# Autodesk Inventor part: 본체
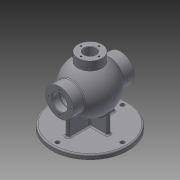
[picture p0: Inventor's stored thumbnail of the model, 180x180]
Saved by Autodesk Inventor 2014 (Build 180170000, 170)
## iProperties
Created: 2020-08
Part Number: 본체
Material: Generic
Document SubType Name: Modeling
Designer: kh
Density: 1 g/cm^3
Appearance: Default
Author: kh
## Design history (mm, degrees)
sketch "Sketch1"
  geometry: C1 r 85 at (0, 0); 1 further point
  constraints: 1 centre point, 1 coincident
  dimensions: "d0" = 170 diameter of C1
extrude "Extrusion1" new body sketch "Sketch1" distance "d1" = 10; taper "d2" = 0 deg
sketch "Sketch2"
  geometry: L1 (-68, 85)-(68, 85); A1 r 53 centre (0, 85) between (53, 85) and (-53, 85); 2 further points
  constraints: 2 end point, 2 point on circle, 2 point on line, 1 centre point, 1 coincident, 1 horizontal, 1 midpoint, 1 vertical alignment
  dimensions: "d3" = 136 distance of L1.start L1.end; "d4" = 85 distance from line of point (0, 0) L1; "d5" = 106 diameter of A1
revolve "Revolution1" sketch "Sketch2" stored, may be unused: angle "d6" = 90 deg
sketch "Sketch4"
  geometry: L1 (-68, 85)-(68, 85); L2 (-68, 102.5)-(-68, 116); L3 (-68, 116)-(-42.988, 116); L4 (-68, 102.5)-(-50.027, 102.5); L5 (-50.027, 102.5)-(-42.988, 102.5); L6 (-42.988, 116)-(-42.988, 102.5); A1 r 53 centre (0, 85) between (-42.988, 116) and (-50.027, 102.5) reference; 2 further points
  constraints: 12 end point, 3 perpendicular, 2 point on circle, 1 coincident, 1 collinear, 1 horizontal, 1 midpoint, 1 parallel, 1 vertical alignment
  dimensions: "d7" = 85 distance from line of point (0, 0) L1; "d8" = 136 distance of L1.start L1.end; "d9" = 35 diameter of L2.start L1; "d10" = 62 diameter of L2.end L1
revolve "Revolution2" sketch "Sketch4" stored, may be unused: angle "d11" = 90 deg
mirror "Mirror1"
sketch "Sketch5"
  geometry: L1 (43, 85)-(-43, 85); A1 r 53 centre (0, 85) between (42.988, 116) and (42.988, 54) reference; A2 r 53 centre (0, 85) between (50.027, 67.5) and (50.027, 102.5) reference; A3 r 53 centre (0, 85) between (50.027, 102.5) and (42.988, 116); A4 r 53 centre (0, 85) between (42.988, 54) and (50.027, 67.5); A5 r 43 centre (0, 85) between (-43, 85) and (43, 85); 1 further point
  constraints: 6 point on circle, 3 centre point, 3 coincident, 2 end point, 1 horizontal, 1 midpoint
  dimensions: "d12" = 86 diameter of A5
revolve "Revolution3" sketch "Sketch5" stored, may be unused: angle "d13" = 90 deg
workplane "Work Plane1"
sketch "Sketch7"
  geometry: C1 r 17.5 at (0, 0) reference; C2 r 17.5 at (0, 0); 1 further point
  constraints: 1 centre point, 1 coincident, 1 concentric
extrude "Extrusion2" cut sketch "Sketch7" stored distance "d15" = 10; taper "d16" = 0 deg
workplane "Work Plane2"
sketch "Sketch8"
  geometry: C1 r 27 at (0, 0); 1 further point
  constraints: 1 centre point, 1 coincident
  dimensions: "d18" = 54 diameter of C1
extrude "Extrusion3" join sketch "Sketch8" stored distance "d19" = 10; taper "d20" = 0 deg
sketch "Sketch9"
  geometry: C1 r 13 at (0, 0); 1 further point
  constraints: 1 centre point, 1 coincident
  dimensions: "d21" = 26 diameter of C1
extrude "Extrusion4" cut sketch "Sketch9" stored distance "d22" = 10; taper "d23" = 0 deg
sketch "Sketch10"
  geometry: 2 further points
  constraints: 1 vertical alignment
  dimensions: "d24" = 20 distance of point (0, 0) point (0, 20)
hole "Hole1" sketch "Sketch10" at (0, 20) diameter "d25" = 3.459; stored, may be unused: countersink angle "d29" = 90 deg, drill point angle "d31" = 118 deg; dims "d26" = 12, "d27" = 4, "d28" = 2, "d30" = 15
pattern_circular "Circular Pattern1" dims angle "d33" = 360 deg
sketch "Sketch11" dims "d35" = 48
  geometry: C1 r 31 at (0, 0) reference; 3 further points
  constraints: 2 vertical alignment, 1 coincident, 2 other
hole "Hole2" sketch "Sketch11" at (0, 24) diameter "d36" = 3.459; stored, may be unused: countersink angle "d40" = 90 deg, drill point angle "d42" = 118 deg; dims "d37" = 12, "d38" = 4, "d39" = 2, "d41" = 15
pattern_circular "Circular Pattern2" dims angle "d44" = 360 deg
mirror "Mirror2"
sketch "Sketch12"
  geometry: L1 (-4, -52)-(4, -52); L2 (4, -52)-(4, 52); L3 (4, 52)-(-4, 52); L4 (-4, 52)-(-4, -52); L5 (-4, -52)-(4, 52); L6 (4, -52)-(-4, 52); L7 (-43, -4)-(43, -4); L8 (43, -4)-(43, 4); L9 (43, 4)-(-43, 4); L10 (-43, 4)-(-43, -4); L11 (-43, -4)-(43, 4); L12 (43, -4)-(-43, 4); 1 further point
  constraints: 24 end point, 4 midpoint, 4 parallel, 2 horizontal, 2 perpendicular
  dimensions: "d47" = 8 distance of L3.end L2.end; "d48" = 104 distance of L2.end L1.end; "d49" = 86 distance of L9.end L8.end; "d50" = 8 distance of L8.end L7.end
extrude "Extrusion5" join sketch "Sketch12" stored distance "d51" = 10; taper "d52" = 0 deg
chamfer "Chamfer1" distance "d53" = 1; stored, may be unused: second distance "d54" = 2, angle "d55" = 45 deg
chamfer "Chamfer2" distance "d56" = 1; stored, may be unused: second distance "d57" = 2, angle "d58" = 45 deg
chamfer "Chamfer3" distance "d59" = 1; stored, may be unused: second distance "d60" = 2, angle "d61" = 45 deg
sketch "Sketch13"
  geometry: L1 (0, 85)-(-80.895, 85); L2 (-52, 85)-(-52, 103.5); L3 (-52, 103.5)-(-50.25, 103.5); L4 (-50.25, 103.5)-(-50.25, 85); L5 (-68, 103.5)-(-68, 66.5) reference; A1 r 43 centre (0, 85) between (-39.278, 67.5) and (-39.278, 102.5) reference; 1 further point
  constraints: 8 end point, 2 perpendicular, 2 point on line, 1 horizontal, 1 parallel
  dimensions: "d62" = 1.75 distance of L2.end L3.end; "d63" = 16 distance between parallel lines of L5 L2; "d64" = 37 diameter of L3 L1
revolve "Revolution4" sketch "Sketch13" stored, may be unused: angle "d65" = 90 deg
sketch "Sketch14" dims "d66" = 145
  geometry: C1 r 4.5 at (0, 72.5); 2 further points
  constraints: 2 vertical alignment, 1 centre point, 1 coincident, 2 other
  dimensions: "d67" = 9 diameter of C1
extrude "Extrusion6" cut sketch "Sketch14" stored distance "d68" = 10; taper "d69" = 0 deg
pattern_circular "Circular Pattern3" dims angle "d71" = 360 deg
fillet "Fillet1" dims "d73" = 3
fillet "Fillet2" dims "d74" = 3
fillet "Fillet3" dims "d75" = 3
fillet "Fillet4" dims "d76" = 3
workplane "Work Plane3"
sketch "Sketch15"
  geometry: L1 (-14.532, -3.954)-(14.532, -3.954); L2 (14.532, -3.954)-(14.532, -14.046); L3 (14.532, -14.046)-(-14.532, -14.046); L4 (-14.532, -14.046)-(-14.532, -3.954); L5 (-14.532, -14.046)-(14.532, -3.954); L6 (-27, 0)-(27, 0) reference; L7 (-27, 0)-(-27, -19.393) reference; 2 further points
  constraints: 2 end point, 1 midpoint, 2 other
  dimensions: "d77" = 27 horizontal distance of L6.start point (0, -9); "d78" = 9 vertical distance of point (0, -9) L6.start
emboss "Emboss1" sketch "Sketch15" dims "d79" = 0.5, "d80" = 0
body "Solid1"
other parameters: "d14" = 0
